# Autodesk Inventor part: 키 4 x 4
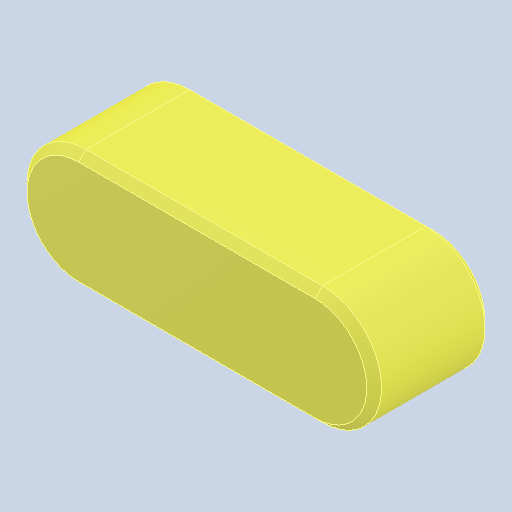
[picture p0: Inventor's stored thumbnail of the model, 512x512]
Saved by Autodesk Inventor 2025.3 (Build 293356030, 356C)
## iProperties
Created: 2025-08
Part Number: 키 4 x 4
Material: 강철, 연강
Description: 키 및 해당 키홈
Document SubType Name: Modeling
Designer: user
Density: 7.86 g/cm^3
Appearance: 기본값
Sending System: Autodesk Inventor 2026
Preprocessor: ST-DEVELOPER v20.1
Author: jhkim
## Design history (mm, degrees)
sketch "스케치1"
  geometry: 1 further point
  constraints: 1 other
feature "Solid1"
node "솔리드1"
